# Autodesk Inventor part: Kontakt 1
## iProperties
Created: 2005-11
Part Number: Kontakt 1
Document SubType Name: Modeling
Designer: Karl-Axel B
Author: Karl-Axel B
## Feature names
1. Extrusion1
2. Extrusion2
3. Chamfer1
